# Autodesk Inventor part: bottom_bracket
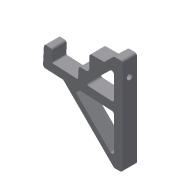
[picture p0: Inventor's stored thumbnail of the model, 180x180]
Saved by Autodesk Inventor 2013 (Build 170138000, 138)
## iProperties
Created: 2013-11
Part Number: bottom_bracket
Material: Generic
Document SubType Name: Modeling
Designer: Jonas
Density: 1 g/cm^3
Author: Jonas
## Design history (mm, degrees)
sketch "Sketch5"
  geometry: L1 (0, 0)-(0, 40); L2 (0, 40)-(7, 40); L3 (7, 40)-(7, 7); L4 (58.71, 9.71)-(58.185, 19.71); L5 (58.185, 19.71)-(65.185, 20.077); L6 (65.185, 20.077)-(66.075, 3.096); L7 (66.075, 3.096)-(7, 0); L8 (7, 0)-(7, -40); L9 (7, -40)-(0, -40); L10 (0, -40)-(0, 0); L11 (0, 0)-(100, 0); L12 (36.939, 8.569)-(36.415, 18.569); L13 (36.415, 18.569)-(29.415, 18.202); L14 (29.415, 18.202)-(29.939, 8.202); L15 (7, 7)-(29.939, 8.202); L16 (36.939, 8.569)-(58.71, 9.71)
  constraints: 32 end point, 7 parallel, 6 perpendicular, 3 equal length, 2 point on line, 1 collinear, 1 horizontal, 1 vertical
  dimensions: "d55" = 7 distance of L1.end L2.end; "d57" = 7 distance of L7.end L3.end (= d55); "d58" = 100 distance of L1.start L11.end; "d59" = 3 deg angle of L7 L11 (= theta); "d60" = 40 distance of L1.start L1.end; "d61" = 40 distance of L9.end L1.start; "d62" = 7 horizontal distance of L4.end L5.end; "d63" = 10 vertical distance of L4.start L4.end; "d69" = 21.8 distance between parallel lines of L4 L12 (computed from frame_thickness); "d105" = 58.70952 distance from line of L1 L4.start (derived)
extrude "Extrusion3" new body sketch "Sketch5" distance "d64" = 12; taper "d65" = 0 deg
sketch "Sketch6"
  geometry: L1 (-66.075, 3.096)-(-7, 0) reference; L2 (-7, 0)-(-7, -40) reference; L3 (-7, -40)-(-49.212, 2.212); L4 (-7, -40)-(52.697, -40); L5 (-49.212, 2.212)-(-42.222, 1.846); L6 (-42.222, 1.846)-(-7, -33.376); L7 (-7, 40)-(-7, 7) reference; L8 (-7, 7)-(-29.939, 8.202) reference; L9 (-7, 40)-(37.914, 40); L10 (-36.939, 8.569)-(-31.033, 8.26); L11 (-31.033, 8.26)-(-7, 31.631); L12 (-36.415, 18.569)-(-36.939, 8.569) reference; L13 (-36.939, 8.569)-(-36.811, 11.01); L14 (0, -40)-(0, 40) reference; L15 (0, 40)-(-7, 40) reference; L16 (0, 26)-(-35, 26); L17 (-15.227, 32)-(-27.567, 32); L18 (-27.567, 32)-(-27.567, 20); L19 (-7, 40)-(-15.227, 32); L20 (-27.567, 20)-(-36.811, 11.01); L21 (-7, -40)-(0, -40) reference; L22 (-7, 40)-(-7, 31.631); 3 further points
  constraints: 28 end point, 11 point on line, 3 horizontal, 3 parallel, 3 perpendicular, 1 equal length
  dimensions: "d70" = 135 deg angle of L4 L3; "d71" = 7 distance of L3.end L5.end; "d75" = 7 distance of point (-38.024, 8.626) L10.end; "d108" = 14 distance between parallel lines of L15 L16; "d109" = 35 distance of L16.start L16.end; "d110" = 12 distance of L17.end L18.end; "d112" = 6 distance between parallel lines of L17 L16 (derived); "d113" = 6 distance between parallel lines of L11 L20
extrude "Extrusion4" join sketch "Sketch6" stored distance "d72" = 10; taper "d73" = 0 deg
sketch "Sketch12"
  geometry: L1 (80, 0)-(80, 12) reference; L2 (0, 0)-(0, 12) reference; L3 (80, 6)-(0, 6); 2 further points
  constraints: 2 end point, 2 midpoint, 1 point on line
  dimensions: "d92" = 14 distance from line of point (14, 6) L2
hole "Hole3" sketch "Sketch12" at (14, 6) diameter "d93" = 4.7; stored, may be unused: countersink angle "d97" = 90 deg, drill point angle "d99" = 118 deg; dims "d94" = 6, "d95" = 4, "d96" = 2, "d98" = 8
fillet "Fillet2" dims "d103" = 2
fillet "Fillet3" dims "d104" = 1
body "Solid3"
other parameters: "theta" = 3 deg, "sprocket_wall_clearance" = 1, "ball_diameter" = 2.45, "ball_distance" = 0.76, "frame_thickness" = 21.5, "d2" = 5
